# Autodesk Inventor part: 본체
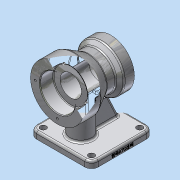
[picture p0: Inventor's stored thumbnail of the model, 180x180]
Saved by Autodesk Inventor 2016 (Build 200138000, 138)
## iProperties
Created: 2019-01
Part Number: 본체
Material: 알루미늄 6061
Document SubType Name: Modeling
Designer: MIRAE
Density: 2.7 g/cm^3
Appearance: 알루미늄 - 평지
Mass: 898.816 g
Surface Area: 600.964 cm^2
Volume: 332.895 cm^3
Author: MIRAE
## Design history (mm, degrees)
sketch "스케치1"
  geometry: L1 (29, 0)-(-51, 0); L2 (-51, 40)-(-26, 40); L3 (-26, 40)-(-5.215, 28); L4 (-5.215, 28)-(8.126, 28); L5 (14, 35)-(29, 35); L6 (29, 35)-(29, 0); L7 (-51, 0)-(-51, 40); L8 (8.126, 28)-(14, 35); 1 further point
  constraints: 16 end point, 2 parallel, 1 horizontal, 1 perpendicular, 1 vertical
  dimensions: "d7" = 80 distance of L1.start L1.end; "d8" = 35 distance of L5.end L1.start; "d9" = 15 distance of L5.start L5.end; "d10" = 25 distance of L2.start L2.end; "d12" = 28 distance between parallel lines of L1 L4; "d13" = 0 distance from line of point (0, 0) L1; "d15" = 40 distance of L1.end L2.start; "d16" = 51 distance from line of L7 point (0, 0); "d17" = 30 deg angle of L4 L3; "d18" = 50 deg angle of L8 L4
revolve "회전1" sketch "스케치1" stored, may be unused: angle "d19" = 90 deg
sketch "스케치2"
  geometry: L1 (29, 0)-(-51, 0); L2 (-51, 0)-(-51, 26); L3 (-51, 26)-(-31, 26); L4 (-31, 26)-(-31, 16); L5 (-31, 16)-(12, 16); L6 (12, 16)-(12, 20); L7 (12, 20)-(29, 20); L8 (29, 20)-(29, 0); L9 (-51, -40)-(-51, 40) reference; L10 (29, -35)-(29, 35) reference; 1 further point
  constraints: 16 end point, 7 perpendicular, 1 horizontal
  dimensions: "d20" = 0 distance from line of point (0, 0) L1; "d21" = 0 distance between parallel lines of L9 L2; "d22" = 0 distance between parallel lines of L10 L8; "d23" = 20 distance of L2.end L3.end; "d24" = 17 distance of L6.end L7.end; "d25" = 20 distance between parallel lines of L1 L7; "d26" = 26 distance between parallel lines of L1 L3; "d27" = 16 distance between parallel lines of L1 L5
revolve "회전2" sketch "스케치2" stored, may be unused: angle "d28" = 90 deg
fillet "모깎기1" dims "d29" = 1
fillet "모깎기2" dims "d30" = 0.6
chamfer "모따기1" distance "d31" = 1; stored, may be unused: second distance "d32" = 2, angle "d33" = 45 deg
fillet "모깎기3" dims "d34" = 3
sketch "스케치3"
  geometry: 2 further points
  dimensions: "d35" = 0 horizontal distance of point (0, 0) point (0, 33); "d36" = 33 distance of point (0, 0) point (0, 33)
hole "구멍1" sketch "스케치3" at (0, 33) diameter "d37" = 3.242; stored, may be unused: countersink angle "d41" = 90 deg, drill point angle "d43" = 118 deg; dims "d38" = 9, "d39" = 4, "d40" = 2, "d42" = 11
sketch "스케치4"
  geometry: 2 further points
  dimensions: "d47" = 27.5 distance of point (0, 0) point (0, -27.5); "d48" = 0 horizontal distance of point (0, 0) point (0, -27.5)
hole "구멍2" sketch "스케치4" at (0, -27.5) diameter "d49" = 3.242; stored, may be unused: countersink angle "d53" = 90 deg, drill point angle "d55" = 118 deg; dims "d50" = 9, "d51" = 4, "d52" = 2, "d54" = 11
node "작업 평면1"
sketch "스케치5"
  geometry: L1 (46, 46)-(-46, 46); L2 (-46, 46)-(-46, -46); L3 (-46, -46)-(46, -46); L4 (46, -46)-(46, 46); L5 (46, 46)-(-46, -46); L6 (-46, 46)-(46, -46); 1 further point
  constraints: 12 end point, 2 midpoint, 2 parallel, 1 horizontal, 1 perpendicular
  dimensions: "d60" = 92 distance of L3.end L1.start; "d61" = 92 distance of L1.start L1.end
extrude "돌출1" join sketch "스케치5" distance "d62" = 10; taper "d63" = 0 deg
fillet "모깎기4" dims "d64" = 10
fillet "모깎기5" dims "d65" = 3
sketch "스케치6"
  geometry: C1 r 4.5 at (-36, 36); C2 r 4.5 at (-36, -36); C3 r 4.5 at (36, -36); C4 r 4.5 at (36, 36); A1 r 10 centre (-36, 36) between (-36, 46) and (-46, 36) reference; A2 r 10 centre (-36, -36) between (-46, -36) and (-36, -46) reference; A3 r 10 centre (36, -36) between (36, -46) and (46, -36) reference; A4 r 10 centre (36, 36) between (46, 36) and (36, 46) reference; 1 further point
  constraints: 4 centre point, 4 coincident
  dimensions: "d66" = 9 diameter of C1; "d67" = 9 diameter of C2; "d68" = 9 diameter of C3; "d69" = 9 diameter of C4
extrude "돌출2" cut sketch "스케치6" stored distance "d70" = 10; taper "d71" = 0 deg
sketch "스케치7"
  geometry: L1 (-36, -46)-(36, -46) reference; C1 r 16 at (0, -16); 1 further point
  constraints: 1 centre point
  dimensions: "d72" = 32 diameter of C1; "d73" = 0 horizontal distance of C1.centre point (0, 0); "d74" = 30 distance from line of C1.centre L1
extrude "돌출3" join sketch "스케치7" stored distance "d75" = 10; taper "d76" = 0 deg
sketch "스케치8"
  geometry: L1 (21.594, -39.107)-(36, -70); L2 (36, -70)-(-36, -70) reference; L3 (46, -80)-(46, -73) reference; 1 further point
  constraints: 2 end point
  dimensions: "d77" = 0 distance from line of L1.end L2; "d78" = 10 distance from line of L3 L1.end; "d79" = 25 deg angle of L3 L1
feature "리브1" sketch "스케치8" dims "d80" = 1, "d81" = 10, "d82" = 0, "d83" = 0, "d84" = 1, "d85" = 1
fillet "모깎기6" dims "d86" = 3
fillet "모깎기7" dims "d87" = 3
fillet "모깎기8" dims "d88" = 3
fillet "모깎기9" dims "d89" = 3
sketch "스케치9"
  geometry: L1 (-7, -10)-(0, -10) reference; L2 (0, 0)-(0, 72) reference; 2 further points
  constraints: 1 other
  dimensions: "d90" = 46 distance from line of L1 point (-4, 36); "d91" = 4 distance from line of L2 point (-4, 36)
feature "엠보싱1" sketch "스케치9" dims "d20" = 0, "d21" = 0, "d22" = 0, "d23" = 20, "d24" = 17, "d25" = 20, "d26" = 26, "d27" = 16, "d92" = 0.5, "d93" = 0
feature "분할1"
node "솔리드1"
pattern_circular "원형 패턴1" dims angle "d45" = 360 deg
pattern_circular "원형 패턴2" dims angle "d57" = 360 deg
